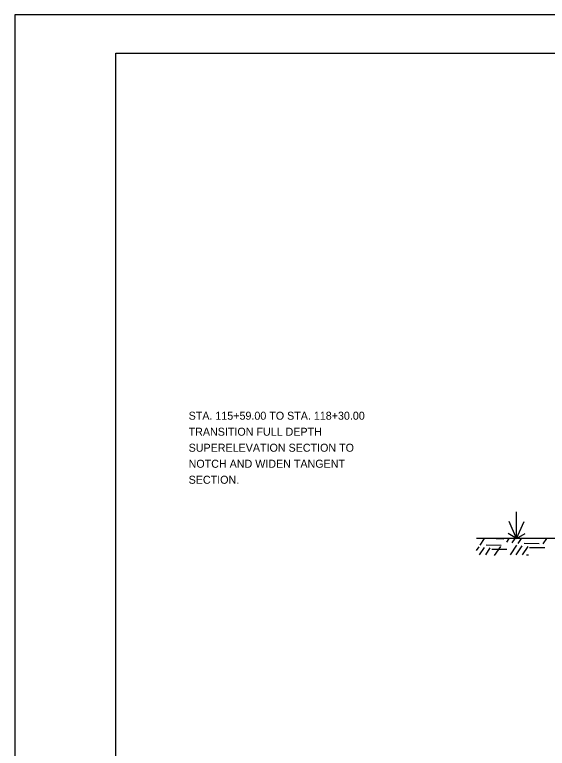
# Model space of a CAD drawing. Extents: x 2478 to 3210, y 439 to 841.
# Drawn here: x 2477.8 to 2557.7, y 548.6 to 658.6 of the extents above; entities that cross this region are included whole.
import ezdxf

# ---------------------------------------------------------------- set-up
doc = ezdxf.new("R2010")
doc.units = 0
for name, color, linetype in [('1', 7, 'Continuous'), ('R_Annotation', 7, 'Continuous'), ('R_Dimension', 7, 'Continuous'), ('R_Draft', 7, 'Continuous')]:
    doc.layers.add(name, color=color, linetype=linetype)

msp = doc.modelspace()

# ---------------------------------------------------------------- linework, layer by layer
at = {"layer": '1'}
for p, q in [((2492.97, 652.81), (2812.04, 652.81)), ((2492.97, 444.35), (2492.97, 652.81))]:
    msp.add_line(p, q, dxfattribs=at)
for points in [[(2817.81, 658.58), (2477.81, 658.58), (2477.81, 438.58), (2817.81, 438.58)], [(2492.97, 444.35), (2492.97, 652.81), (2729.78, 652.81), (2729.78, 642.93), (2768.94, 642.93), (2768.94, 640.01), (2812.04, 640.01), (2812.04, 444.35)]]:
    msp.add_lwpolyline(points, close=True, dxfattribs=at)
at = {"layer": 'R_Annotation'}
msp.add_line((2559.07, 580.02), (2547.07, 580.02), dxfattribs=at)
at = {"layer": 'R_Dimension'}
for p, q in [((2547.62, 579.04), (2548.27, 580.02)), ((2550.01, 580.02), (2551.16, 580.01)), ((2551.6, 579.47), (2551.97, 580.02)), ((2552.4, 579.38), (2552.83, 580.02)), ((2553.29, 579.28), (2553.78, 580.02)), ((2557.05, 579.23), (2557.58, 580.02)), ((2547.07, 578.26), (2547.43, 578.8)), ((2547.49, 577.61), (2548.23, 578.71)), ((2548.44, 577.61), (2549.12, 578.62)), ((2548.51, 579.08), (2550.77, 579.06)), ((2549.77, 577.47), (2550.7, 578.85)), ((2552.14, 577.61), (2553.1, 579.04)), ((2553, 577.61), (2553.9, 578.95)), ((2553.95, 577.61), (2554.79, 578.86)), ((2554.18, 579.32), (2556.44, 579.3)), ((2555.01, 578.69), (2557.28, 578.67)), ((2549.34, 578.45), (2551.6, 578.43)), ((2554.57, 577.61), (2554.84, 577.61))]:
    msp.add_line(p, q, dxfattribs=at)
at = {"layer": 'R_Draft'}
for q in [(2553.07, 584.03), (2551.93, 582.6), (2554.21, 582.6), (2551.81, 580.77), (2554.33, 580.77)]:
    msp.add_line((2553.07, 580.02), q, dxfattribs=at)

# ---------------------------------------------------------------- texts
at = {"layer": 'R_Annotation'}
for s, p in [('STA. 115+59.00 TO STA. 118+30.00', (2503.89, 597.85)), ('TRANSITION FULL DEPTH ', (2503.89, 595.45)), ('SUPERELEVATION SECTION TO', (2503.89, 593.05)), ('NOTCH AND WIDEN TANGENT ', (2503.89, 590.65)), ('SECTION.', (2503.89, 588.25))]:
    msp.add_text(s, height=1.2, dxfattribs=at).set_placement(p)

doc.saveas('drawing.dxf')
